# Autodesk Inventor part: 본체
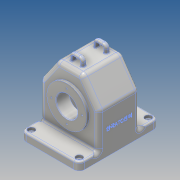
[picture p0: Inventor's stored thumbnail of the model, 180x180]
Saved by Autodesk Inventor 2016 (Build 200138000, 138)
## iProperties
Created: 2016-12
Part Number: 본체
Material: 알루미늄 6061
Document SubType Name: Modeling
Designer: Administrator
Density: 2.7 g/cm^3
Appearance: 알루미늄 - 평지
Mass: 1007.38 g
Surface Area: 1133.9 cm^2
Volume: 373.102 cm^3
Author: Administrator
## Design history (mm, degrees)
sketch "스케치1"
  geometry: L1 (-75, 55)-(75, 55); L2 (75, 55)-(75, -55); L3 (75, -55)-(-75, -55); L4 (-75, -55)-(-75, 55); 3 further points
  constraints: 8 end point, 2 midpoint, 2 parallel, 1 horizontal, 1 horizontal alignment, 1 perpendicular, 1 vertical alignment
  dimensions: "d0" = 150 distance between parallel lines of L2 L4; "d1" = 110 distance between parallel lines of L3 L1
extrude "돌출1" new body sketch "스케치1" distance "d2" = 15; taper "d3" = 0 deg
fillet "모깎기1" dims "d4" = 10
sketch "스케치3"
  geometry: A1 r 10 centre (65, 45) between (75, 45) and (65, 55) reference; A2 r 10 centre (-65, 45) between (-65, 55) and (-75, 45) reference; A3 r 10 centre (-65, -45) between (-75, -45) and (-65, -55) reference; A4 r 10 centre (65, -45) between (65, -55) and (75, -45) reference; 5 further points
  constraints: 4 coincident
hole "구멍1" sketch "스케치3" at (-65, 45), (65, 45), (65, -45), (-65, -45) diameter "d5" = 5; stored, may be unused: countersink angle "d9" = 90 deg, drill point angle "d11" = 0 deg; dims "d6" = 6, "d7" = 12, "d8" = 5, "d10" = 8
sketch "스케치4"
  geometry: L1 (-55, 0)-(-55, 15) reference; L2 (55, 15)-(55, 0) reference; L3 (45, 15)-(55, 15) reference; L4 (-51, 15)-(-39, 15) reference; L5 (-55, 15)-(-45, 15) reference; L6 (-55, 0)-(-55, 80); L7 (-55, 80)-(55, 80); L8 (55, 0)-(45, 0) reference; L9 (55, 80)-(55, 0); L10 (-55, 80)-(-23.491, 125); L11 (-23.491, 125)-(23.491, 125); L12 (23.491, 125)-(55, 80); L13 (-45, 0)-(45, 0) reference; L14 (-55, 0)-(55, 0); 1 further point
  constraints: 14 end point, 2 horizontal, 2 perpendicular, 1 vertical
  dimensions: "d12" = 80 distance of L1.start L6.end; "d13" = 35 deg angle of L10 L6; "d14" = 35 deg angle of L9 L12; "d15" = 125 distance between parallel lines of L11 L13
extrude "돌출2" join sketch "스케치4" stored distance "d16" = 77; taper "d17" = 0 deg
sketch "스케치9"
  geometry: L1 (50, 0)-(50, 78.424); L2 (20.888, 120)-(-20.888, 120); L3 (-50, 78.424)-(-50, 0); L4 (-50, 0)-(50, 0); L5 (55, 15)-(-55, 15) reference; L6 (55, 15)-(55, 80) reference; L7 (55, 80)-(23.491, 125) reference; L8 (23.491, 125)-(-23.491, 125) reference; L9 (-23.491, 125)-(-55, 80) reference; L10 (-55, 80)-(-55, 15) reference; L11 (20.888, 120)-(50, 78.424); L12 (-20.888, 120)-(-50, 78.424); 3 further points
  constraints: 12 end point, 3 parallel, 2 midpoint, 2 perpendicular, 1 coincident, 1 vertical, 1 vertical alignment
  dimensions: "d34" = 5 distance between parallel lines of L8 L2; "d35" = 5 distance between parallel lines of L6 L1; "d112" = 5 distance between parallel lines of L11 L7; "d115" = 5 distance between parallel lines of L9 L12; "d116" = 5 distance between parallel lines of L10 L3
extrude "돌출4" cut sketch "스케치9" stored distance "d36" = 67; taper "d37" = 0 deg
sketch "스케치10"
  geometry: L1 (43.5, 65)-(-48.5, 65); L2 (38.5, 80)-(38.5, 15) reference; L3 (43.5, 85)-(43.5, 102.5); L4 (-48.5, 85)-(-48.5, 96); L5 (-48.5, 96)-(-33.5, 96); L6 (-33.5, 96)-(-33.5, 85); L7 (-33.5, 0)-(-33.5, 78.424) reference; L8 (-33.5, 85)-(-48.5, 85); L9 (19.5, 92)-(19.5, 85); L10 (19.5, 85)-(43.5, 85); L11 (19.5, 92)-(30, 102.5); L12 (30, 102.5)-(43.5, 102.5); 2 further points
  constraints: 20 end point, 4 vertical, 3 horizontal, 2 perpendicular, 2 vertical alignment
  dimensions: "d38" = 92 distance of L1.start L1.end; "d39" = 5 distance from line of L2 L1.start; "d40" = 65 distance from line of point (0, 0) L1; "d45" = 15 distance between parallel lines of L4 L6; "d46" = 62 diameter of L5 L1; "d50" = 24 distance between parallel lines of L9 L3; "d51" = 40 diameter of L10 L1; "d53" = 40 diameter of L8 L1; "d106" = 54 diameter of L9.start L1; "d107" = 45 deg angle of L11 L9; "d108" = 75 diameter of L12 L1
revolve "회전1" sketch "스케치10" stored, may be unused: angle "d47" = 90 deg
sketch "스케치11"
  geometry: C1 r 20 at (0, 0) reference; C2 r 37.5 at (0, 0) reference; C3 r 20 at (0, 0); 1 further point
  constraints: 1 centre point, 1 coincident, 1 concentric
extrude "돌출5" cut sketch "스케치11" stored distance "d48" = 67; taper "d49" = 0 deg
node "작업 평면1"
sketch "스케치14"
  geometry: L1 (-23.491, 125)-(23.491, 125) reference; L2 (0, 125)-(0, 140); L3 (-12.5, 140)-(12.5, 140); L4 (12.5, 140)-(12.5, 125); L5 (-12.5, 140)-(-12.5, 125); L6 (-7.5, 125)-(-7.5, 135); L7 (-7.5, 135)-(7.5, 135); L8 (7.5, 135)-(7.5, 125); 6 further points
  constraints: 14 end point, 8 point on line, 5 midpoint, 3 perpendicular, 3 vertical, 3 vertical alignment, 1 horizontal
  dimensions: "d57" = 25 distance between parallel lines of L4 L5; "d58" = 140 distance from line of L3 point (0, 0); "d64" = 5 distance between parallel lines of L3 L7; "d93" = 15 distance between parallel lines of L8 L6
extrude "돌출6" join sketch "스케치14" distance "d65" = 8; taper "d66" = 0 deg
fillet "모깎기2" dims "d67" = 1
sketch "스케치17"
  geometry: C1 r 20 at (0, 0) reference; C2 r 31 at (0, 0) reference; A1 r 26 centre (0, 0) between (-26, 0) and (0, 26); 3 further points
  constraints: 4 point on circle, 2 horizontal alignment, 2 vertical alignment, 1 centre point, 1 coincident
  dimensions: "d68" = 52 diameter of A1
hole "구멍2" sketch "스케치17" at (-26, 0), (0, 26), (26, 0), (0, -26) diameter "d69" = 2.459; stored, may be unused: countersink angle "d73" = 90 deg, drill point angle "d75" = 118 deg; dims "d70" = 6, "d71" = 12, "d72" = 5, "d74" = 8
node "작업 평면3"
sketch "스케치19"
  geometry: L1 (-103.5, 15)-(-103.5, 80) reference; 2 further points
  constraints: 1 other
  dimensions: "d76" = 45 distance of point (-65, 45) point (-65, 0); "d77" = 38.5 distance from line of point (-65, 45) L1
feature "엠보싱1" sketch "스케치19" dims "d0" = 150, "d1" = 110, "d78" = 0.5, "d79" = 0
sketch "스케치21"
  geometry: C1 r 20 at (0, 0) reference; C2 r 37.5 at (0, 0) reference; A1 r 29 centre (0, 0) between (29, 0) and (0, -29); 3 further points
  constraints: 4 point on circle, 2 horizontal alignment, 2 vertical alignment, 1 centre point, 1 coincident
  dimensions: "d80" = 58 diameter of A1
hole "구멍3" sketch "스케치21" at (29, 0), (0, -29), (-29, 0), (0, 29) diameter "d81" = 2.459; stored, may be unused: countersink angle "d85" = 90 deg, drill point angle "d87" = 118 deg; dims "d82" = 6, "d83" = 12, "d84" = 5, "d86" = 8
fillet "모깎기3" dims "d88" = 3
fillet "모깎기4" dims "d89" = 3
fillet "모깎기5" dims "d90" = 3
fillet "모깎기6" dims "d91" = 3
fillet "모깎기8" dims "d94" = 8
fillet "모깎기9" dims "d95" = 3
fillet "모깎기10" dims "d96" = 1
fillet "모깎기15" dims "d101" = 3
fillet "모깎기16" dims "d102" = 3
chamfer "모따기1" distance "d103" = 1; stored, may be unused: second distance "d104" = 2, angle "d105" = 45 deg
fillet "모깎기18" dims "d110" = 10
fillet "모깎기19" dims "d111" = 8
node "솔리드1"
mirror "대칭4"
node "투영된 루프1"
other parameters: "d54" = 18, "d114" = 5
